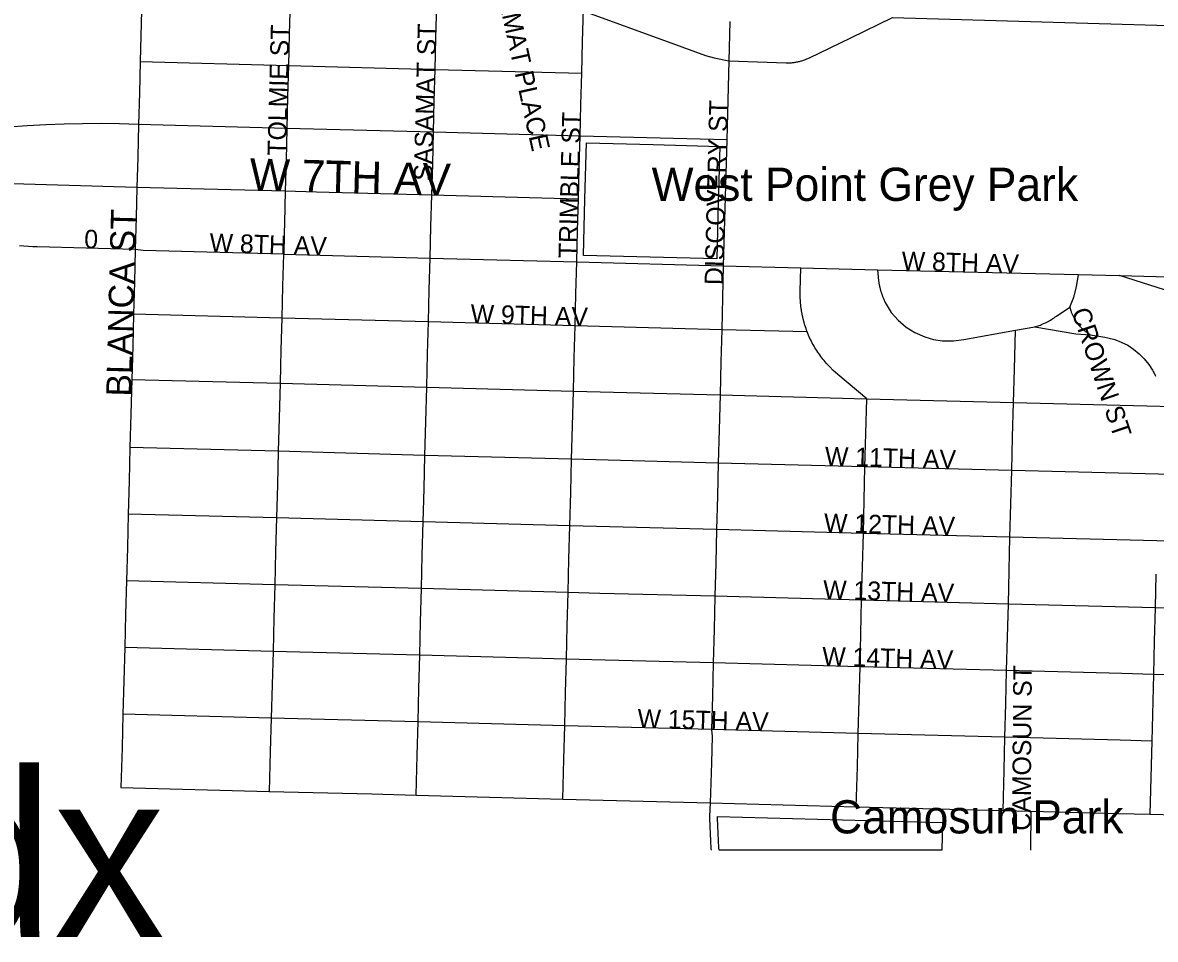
# Model space of a CAD drawing. Extents: x 482780 to 486928, y 5455974 to 5459836.
# Drawn here: x 484178 to 485885, y 5455974 to 5457356 of the extents above; entities that cross this region are included whole.
import ezdxf

# ---------------------------------------------------------------- set-up
doc = ezdxf.new("R2010")
doc.units = 0
for name, color, linetype in [('Default', 7, 'Continuous'), ('ParkLabels', 7, 'Continuous'), ('Parks', 7, 'Continuous'), ('StreetNames', 7, 'Continuous'), ('Streets', 7, 'Continuous')]:
    doc.layers.add(name, color=color, linetype=linetype)

msp = doc.modelspace()

# ---------------------------------------------------------------- linework, layer by layer
at = {"layer": 'Parks'}
for points in [[(485027.7, 5457174.3), (485128.1, 5457171.7), (485228.6, 5457169.1), (485226.3, 5457084.2), (485224.1, 5456999.4), (485123.6, 5457002.1), (485023.2, 5457004.7), (485025.4, 5457089.5)], [(485563.4, 5456108), (485227.7, 5456108), (485227.4, 5456111.7), (485226.6, 5456122.7), (485226, 5456133.8), (485225.6, 5456144.8), (485225.4, 5456155.9), (485225.3, 5456158.8), (485564.5, 5456150.1)]]:
    msp.add_lwpolyline(points, close=True, dxfattribs=at)
at = {"layer": 'Streets'}
for points in [[(484357.5, 5457393.7), (484354.9, 5457296.8), (484353.7, 5457249.5), (484352.4, 5457202.1), (484351.1, 5457152.7), (484349.9, 5457107.3), (484348.6, 5457061.7), (484347.4, 5457013.4), (484346.1, 5456964.3), (484344.8, 5456916.2), (484343.6, 5456868.1), (484342.2, 5456817.9), (484340.8, 5456765.6), (484339.5, 5456715.3), (484338.2, 5456665.1), (484336.8, 5456614.8), (484335.5, 5456564.6), (484334.2, 5456514.3), (484332.8, 5456464), (484331.5, 5456413.8), (484330.2, 5456363.5), (484328.8, 5456313.1), (484327.5, 5456262.8), (484325.9, 5456202.5)], [(484581.1, 5457387.9), (484579.7, 5457338.4), (484578.5, 5457291.1), (484577.2, 5457243.6), (484576, 5457196.2), (484574.7, 5457148.8), (484573.5, 5457101.4), (484572.2, 5457054), (484570.9, 5457006.5), (484569.6, 5456958.4), (484568.4, 5456910.3), (484567.1, 5456862.2), (484565.7, 5456812), (484564.3, 5456759.6), (484563, 5456709.4), (484561.7, 5456659.1), (484560.4, 5456608.9), (484559.1, 5456558.6), (484557.8, 5456508.3), (484556.5, 5456458.1), (484555.1, 5456407.8), (484553.8, 5456357.6), (484552.3, 5456307.3), (484551, 5456257), (484549.4, 5456196.6)], [(484770.8, 5456190.9), (484772.3, 5456251.2), (484773.7, 5456301.5), (484774.9, 5456351.7), (484776.3, 5456402), (484777.5, 5456452.3), (484778.9, 5456502.5), (484780.2, 5456552.7), (484781.5, 5456602.9), (484782.9, 5456653.2), (484784.2, 5456703.3), (484785.5, 5456753.7), (484786.9, 5456806.1), (484788.2, 5456856.3), (484789.4, 5456904.5), (484790.7, 5456952.7), (484791.9, 5457000.8), (484793.2, 5457048.3), (484794.5, 5457095.7), (484795.8, 5457143), (484796.9, 5457190.4), (484798.2, 5457237.7), (484799.5, 5457285.1), (484800.7, 5457332.6), (484802, 5457382.2)], [(484992, 5456185.1), (484993.5, 5456245.4), (484994.8, 5456295.7), (484996.1, 5456345.9), (484997.5, 5456396.1), (484998.7, 5456446.3), (485000, 5456496.5), (485001.3, 5456546.8), (485002.6, 5456597.1), (485004, 5456647.3), (485005.3, 5456697.6), (485006.6, 5456747.8), (485007.9, 5456800.2), (485009.2, 5456850.4), (485010.5, 5456898.6), (485011.7, 5456946.7), (485013, 5456994.9), (485014.2, 5457042.3), (485015.5, 5457089.7), (485016.7, 5457137.1), (485018, 5457184.6), (485019.3, 5457232), (485020.6, 5457279.4), (485021.8, 5457326.8), (485023.2, 5457376.2)], [(485033.1, 5457369.2), (485156.2, 5457324.6), (485206.9, 5457306), (485220.2, 5457302.4), (485242.3, 5457298), (485328.6, 5457295), (485328.9, 5457294.9), (485330.2, 5457294.9), (485331.6, 5457294.9), (485332.9, 5457295), (485334.2, 5457295), (485335.5, 5457295.1), (485336.9, 5457295.2), (485338.2, 5457295.3), (485339.5, 5457295.5), (485340.8, 5457295.6), (485342.2, 5457295.8), (485343.5, 5457296), (485344.8, 5457296.3), (485346.1, 5457296.5), (485347.4, 5457296.8), (485348.7, 5457297.1), (485350, 5457297.4), (485351.2, 5457297.8), (485352.5, 5457298.2), (485353.8, 5457298.6), (485355, 5457299), (485356.3, 5457299.4), (485357.6, 5457299.9), (485358.8, 5457300.4), (485360, 5457300.9), (485361.2, 5457301.4), (485362.4, 5457301.9), (485363.8, 5457302.5), (485426.1, 5457332.6), (485489.1, 5457363.1), (486129.9, 5457344.8)], [(485243.8, 5457357.3), (485242.3, 5457298), (485239, 5457178.9), (485233.9, 5456989.1), (485232.7, 5456940.9), (485231.5, 5456892.7), (485230.3, 5456844.5), (485229, 5456794.3), (485227.7, 5456741.9), (485226.4, 5456691.7), (485225.1, 5456641.6), (485223.8, 5456591.3), (485222.5, 5456541), (485221.3, 5456490.8), (485220, 5456440.6), (485218.7, 5456390.3), (485217.4, 5456340.1), (485216.1, 5456289.8), (485216.9, 5456279.7), (485215.9, 5456239.6), (485214.3, 5456179.3), (485213.2, 5456158.7), (485213.2, 5456155.7), (485213.4, 5456144.5), (485213.9, 5456133.2), (485214.5, 5456121.9), (485215.3, 5456110.7), (485215.5, 5456108)], [(484354.9, 5457296.8), (484578.5, 5457291.1), (484799.5, 5457285.1), (485020.6, 5457279.4)], [(485239, 5457178.9), (485018, 5457184.6), (484796.9, 5457190.4), (484576, 5457196.2), (484352.4, 5457202.1), (484351.8, 5457202.2), (484323.9, 5457203), (484296, 5457203.4), (484268.1, 5457203.3), (484240.3, 5457202.7), (484212.4, 5457201.6), (484184.6, 5457200), (484156.7, 5457198), (484129, 5457195.4), (484101.2, 5457192.4), (484024.9, 5457184)], [(485015.5, 5457089.7), (484794.5, 5457095.7), (484620.7, 5457100.2), (484573.5, 5457101.4), (484349.9, 5457107.3), (484094.2, 5457114.5), (484023.1, 5457116.5)], [(484347.4, 5457013.4), (484199.6, 5457017.5), (484193, 5457017.8), (484186.3, 5457018.2), (484179.6, 5457018.7), (484172.9, 5457019.3)], [(484570.9, 5457006.5), (484359.6, 5457012), (484347.4, 5457013.4)], [(484570.9, 5457006.5), (484791.9, 5457000.8), (485013, 5456994.9), (485233.9, 5456989.1), (485350.6, 5456986.1), (485466.4, 5456983.2), (485769.4, 5456975.7), (485831.1, 5456974.2), (485941.5, 5456971.5), (486040.3, 5456969), (486091.5, 5456967.8), (486340.4, 5456961.5), (486434, 5456958.7)], [(485434.4, 5456173.5), (485436, 5456233.8), (485437.3, 5456284), (485438.7, 5456334.3), (485440, 5456384.6), (485441.3, 5456434.8), (485442.5, 5456485), (485443.8, 5456535.3), (485445.1, 5456585.6), (485446.3, 5456635.8), (485447.5, 5456686), (485448.9, 5456736.3), (485450.2, 5456788.6), (485406.7, 5456825), (485399.5, 5456831.3), (485393.8, 5456837.3), (485390.9, 5456840.4), (485389.2, 5456842.3), (485387.5, 5456844.3), (485385.8, 5456846.3), (485384.1, 5456848.3), (485382.5, 5456850.4), (485380.9, 5456852.5), (485379.3, 5456854.6), (485377.8, 5456856.8), (485376.3, 5456859), (485374.8, 5456861.2), (485373.4, 5456863.4), (485372, 5456865.6), (485370.7, 5456867.9), (485369.4, 5456870.2), (485368.1, 5456872.5), (485366.9, 5456874.9), (485365.7, 5456877.2), (485364.6, 5456879.6), (485363.5, 5456882), (485362.5, 5456884.5), (485361.5, 5456886.9), (485360.5, 5456889.4), (485360.3, 5456889.8), (485359.4, 5456892.2), (485358.6, 5456894.6), (485357.7, 5456897), (485357, 5456899.4), (485356.3, 5456901.8), (485356, 5456902.8), (485355.7, 5456903.7), (485355.6, 5456904.3), (485355.2, 5456905.6), (485354.9, 5456906.6), (485354.7, 5456907.6), (485354.5, 5456908.5), (485354.2, 5456909.4), (485354, 5456910.4), (485353.8, 5456911.4), (485353.6, 5456912.3), (485353.3, 5456913.3), (485353.1, 5456914.2), (485352.9, 5456915.2), (485352.7, 5456916.2), (485352.6, 5456917.1), (485352.4, 5456918.1), (485352.2, 5456919.1), (485352, 5456920), (485351.9, 5456921), (485351.6, 5456922.7), (485351.6, 5456923), (485351.4, 5456923.9), (485351.3, 5456925), (485351.2, 5456925.5), (485351, 5456926.9), (485350.9, 5456927.8), (485350.8, 5456928.8), (485350.7, 5456929.8), (485350.6, 5456930.7), (485350.5, 5456931.7), (485350.4, 5456932.7), (485350.3, 5456933.7), (485350.2, 5456934.7), (485350.1, 5456936.9), (485349.9, 5456940.5), (485349.8, 5456941.5), (485349.8, 5456942.4), (485349.7, 5456943.6), (485349.7, 5456944.7), (485349.7, 5456946.6), (485349.7, 5456946.7), (485349.7, 5456948), (485349.7, 5456948.8), (485349.7, 5456949.8), (485349.8, 5456950.9), (485350.6, 5456986.1)], [(485466.4, 5456983.2), (485467.4, 5456971.9), (485467.5, 5456970.9), (485467.6, 5456969.9), (485467.7, 5456968.9), (485467.8, 5456968), (485467.9, 5456967), (485468, 5456966.1), (485468.2, 5456965.1), (485468.3, 5456964.6), (485468.5, 5456963.2), (485468.6, 5456962.3), (485468.8, 5456961.3), (485469, 5456960.3), (485469.2, 5456959.4), (485469.4, 5456958.4), (485469.6, 5456957.5), (485469.8, 5456956.6), (485470, 5456955.6), (485470.3, 5456954.6), (485470.5, 5456953.7), (485470.8, 5456952.8), (485471, 5456951.9), (485471.3, 5456950.9), (485471.6, 5456950), (485471.9, 5456949.1), (485472.2, 5456948.2), (485472.5, 5456947.2), (485472.8, 5456946.3), (485473.2, 5456945.3), (485473.4, 5456944.5), (485473.8, 5456943.6), (485474.1, 5456942.6), (485474.5, 5456941.8), (485474.8, 5456940.9), (485475.2, 5456939.9), (485478.1, 5456933.8), (485487.1, 5456918.5), (485497.5, 5456907.1), (485509.6, 5456896.5), (485522.8, 5456888.5), (485537.6, 5456881.8), (485550.8, 5456877.9), (485564.2, 5456876.1), (485580.8, 5456876.1), (485596.3, 5456877.7), (485674.3, 5456891.9), (485703.5, 5456897), (485709.9, 5456899), (485711.9, 5456899.8), (485713.8, 5456900.6), (485715.8, 5456901.5), (485717.7, 5456902.4), (485719.6, 5456903.3), (485721.5, 5456904.3), (485723.4, 5456905.3), (485725.3, 5456906.3), (485727.1, 5456907.3), (485729, 5456908.4), (485730.8, 5456909.6), (485732.6, 5456910.7), (485734.4, 5456911.9), (485736.1, 5456913.1), (485756.4, 5456926.8), (485762.1, 5456941.7), (485766.6, 5456957.1), (485769.4, 5456975.7)], [(486434, 5456862.4), (486337.7, 5456864.9), (486290.2, 5456866.4), (486221.7, 5456870), (486131.5, 5456884.3), (486057.9, 5456904), (486003.2, 5456920.6), (485922.7, 5456945.1), (485831.1, 5456974.2)], [(485756.4, 5456926.8), (485756.6, 5456925.7), (485756.9, 5456924.6), (485757.2, 5456923.6), (485757.5, 5456922.5), (485757.8, 5456921.4), (485758.2, 5456920.4), (485758.5, 5456919.3), (485758.9, 5456918.3), (485759.3, 5456917.3), (485759.7, 5456916.2), (485760.2, 5456915.2), (485760.6, 5456914.2), (485761.1, 5456913.2), (485761.6, 5456912.2), (485762.1, 5456911.2), (485762.6, 5456910.2), (485763.1, 5456909.2), (485763.7, 5456908.3), (485764.3, 5456907.3), (485764.9, 5456906.4), (485765.5, 5456905.4), (485766.1, 5456904.5), (485766.7, 5456903.6), (485767.4, 5456902.7), (485768, 5456901.8), (485768.7, 5456901), (485769.4, 5456900.1), (485770.1, 5456899.2), (485770.9, 5456898.4), (485771.6, 5456897.6), (485772.4, 5456896.8), (485773.2, 5456896), (485773.9, 5456895.2), (485774.7, 5456894.4), (485775.6, 5456893.7), (485776.4, 5456892.9), (485777.2, 5456892.2), (485778.1, 5456891.5), (485778.9, 5456890.8), (485779.8, 5456890.1), (485780.7, 5456889.4), (485781.6, 5456888.8), (485782.5, 5456888.1), (485783.4, 5456887.5), (485784.4, 5456886.9), (485785.3, 5456886.3), (485786.3, 5456885.7), (485787.2, 5456885.2), (485787.4, 5456885.1)], [(485360.5, 5456889.4), (485231.5, 5456892.7), (485010.5, 5456898.6), (484789.4, 5456904.5), (484568.4, 5456910.3), (484344.8, 5456916.2)], [(485655.6, 5456167.9), (485657.2, 5456228.2), (485658.4, 5456278.4), (485659.8, 5456328.6), (485661, 5456378.8), (485662.3, 5456429), (485663.6, 5456479.2), (485664.9, 5456529.5), (485666.1, 5456579.8), (485667.5, 5456630.1), (485668.8, 5456680.4), (485670.1, 5456730.7), (485671.5, 5456783.1), (485672.8, 5456833.3), (485674.3, 5456891.9)], [(485703.5, 5456897), (485765.3, 5456886.5), (485787.4, 5456885.1)], [(485787.4, 5456885.1), (485809.2, 5456881.4), (485813.5, 5456880.7), (485823.9, 5456877.9), (485833.9, 5456874), (485843.5, 5456869.2), (485852.5, 5456863.3), (485860.9, 5456856.5), (485868.5, 5456848.9), (485875.3, 5456840.5), (485881.1, 5456831.5), (485882.1, 5456829.6)], [(485882.1, 5456829.6), (485882.8, 5456828.2), (485883.5, 5456826.9), (485884.2, 5456825.5), (485884.8, 5456824.2), (485885.4, 5456822.8)], [(484342.2, 5456817.9), (484565.7, 5456812), (484786.9, 5456806.1), (485007.9, 5456800.2), (485229, 5456794.3), (485450.2, 5456788.6), (485671.5, 5456783.1), (485892.6, 5456777.5), (485939.7, 5456776.3), (486113.6, 5456771.9), (486334.8, 5456766.4), (486434, 5456763.9)], [(486434, 5456661.1), (486423.2, 5456661.4), (486332.4, 5456663.7), (486111, 5456669.3), (485937.1, 5456673.7), (485889.9, 5456674.9), (485668.8, 5456680.4), (485447.5, 5456686), (485226.4, 5456691.7), (485005.3, 5456697.6), (484784.2, 5456703.3), (484563, 5456709.4), (484339.5, 5456715.3)], [(486434, 5456560.5), (486420.6, 5456560.9), (486329.9, 5456563.3), (486283.2, 5456564.3), (486108.6, 5456568.7), (485887.4, 5456574.3), (485666.1, 5456579.8), (485445.1, 5456585.6), (485223.8, 5456591.3), (485002.6, 5456597.1), (484781.5, 5456602.9), (484560.4, 5456608.9), (484336.8, 5456614.8)], [(486434, 5456459.9), (486420.6, 5456460.2), (486327.3, 5456462.6), (486280.6, 5456463.8), (486106, 5456468.2), (485884.8, 5456473.7), (485663.6, 5456479.2), (485442.5, 5456485), (485221.3, 5456490.8), (485047.9, 5456495.3), (485000, 5456496.5), (484778.9, 5456502.5), (484557.8, 5456508.3), (484334.2, 5456514.3)], [(485886.1, 5456524), (485884.8, 5456473.7), (485883.6, 5456423.4), (485882.3, 5456373.2), (485879.7, 5456272.7), (485876.9, 5456162.5)], [(486434, 5456359.3), (486415.2, 5456359.8), (486324.7, 5456362.2), (486103.4, 5456367.6), (485882.3, 5456373.2), (485834.9, 5456374.4), (485661, 5456378.8), (485440, 5456384.6), (485218.7, 5456390.3), (485035.8, 5456395.1), (484997.5, 5456396.1), (484776.3, 5456402), (484555.1, 5456407.8), (484331.5, 5456413.8)], [(485879.7, 5456272.7), (485832.4, 5456273.9), (485658.4, 5456278.4), (485437.3, 5456284), (485216.1, 5456289.8), (484994.8, 5456295.7), (484773.7, 5456301.5), (484552.3, 5456307.3), (484328.8, 5456313.1)], [(484325.9, 5456202.5), (484549.4, 5456196.6), (484704.2, 5456193.1), (484770.8, 5456190.9), (484992, 5456185.1), (485214.3, 5456179.3), (485434.4, 5456173.5), (485655.6, 5456167.9), (485697.4, 5456166.9), (485829.6, 5456163.6), (485876.9, 5456162.5), (485916.8, 5456161.4), (486097.9, 5456156.7), (486117.8, 5456156.2), (486319.2, 5456151.1), (486434, 5456148.1)], [(485697.4, 5456166.9), (485696.9, 5456108)]]:
    msp.add_lwpolyline(points, dxfattribs=at)

# ---------------------------------------------------------------- texts
at = {"layer": 'Default'}
msp.add_text('xvsxvvs dx', height=250, dxfattribs=at).set_placement((482775.8, 5455977.3))
at = {"layer": 'ParkLabels'}
for s, p in [('West Point Grey Park', (485125.9, 5457086.9)), ('Camosun Park', (485394.9, 5456133.4))]:
    msp.add_text(s, height=50, dxfattribs=at).set_placement(p)
at = {"layer": 'StreetNames'}
for s, height, rotation, p in [('SASAMAT PLACE', 28, 282.4248, (484878.6, 5457464.8)), ('TOLMIE ST', 28, 88.4837, (484574.7, 5457154.8)), ('SASAMAT ST', 28, 88.4922, (484795.2, 5457116.8)), ('DISCOVERY ST', 28, 88.5024, (485233.6, 5456959.7)), ('TRIMBLE ST', 28, 88.4964, (485013.4, 5457000.2)), ('W 7TH AV', 48, 358.4552, (484519.3, 5457103.1)), ('BLANCA ST', 38, 88.4809, (484341.5, 5456791.6)), ('0', 28, 358.3682, (484270.2, 5457015.6)), ('W 8TH AV', 28, 358.2388, (484459.1, 5457010)), ('W 8TH AV', 28, 358.5289, (485502.5, 5456982.6)), ('W 9TH AV', 28, 358.4852, (484852.7, 5456902.8)), ('CROWN ST', 28, 288.5594, (485758.5, 5456920.5)), ('W 11TH AV', 28, 358.5166, (485386.8, 5456688.2)), ('W 12TH AV', 28, 358.5166, (485385.4, 5456587.7)), ('W 13TH AV', 28, 358.5154, (485384.1, 5456487.1)), ('W 14TH AV', 28, 358.516, (485382.7, 5456386.6)), ('CAMOSUN ST', 28, 89.5725, (485697.2, 5456137.4)), ('W 15TH AV', 28, 358.5057, (485104.3, 5456292.9))]:
    msp.add_text(s, height=height, rotation=rotation, dxfattribs=at).set_placement(p)

doc.saveas('drawing.dxf')
